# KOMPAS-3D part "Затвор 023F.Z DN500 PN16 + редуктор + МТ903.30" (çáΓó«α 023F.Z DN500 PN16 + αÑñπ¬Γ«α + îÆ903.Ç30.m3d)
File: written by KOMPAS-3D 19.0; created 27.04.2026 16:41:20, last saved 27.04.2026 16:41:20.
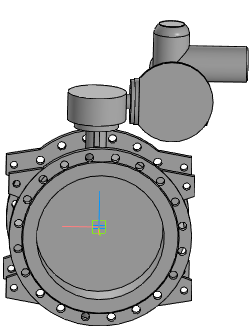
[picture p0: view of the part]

Document properties: Полное имя файла: ..\..\Затвор 023F.Z DN400-DN1600 + редуктор + МТ903\Затвор 023F.Z DN500 PN16 + редуктор + МТ903.А30.a3d

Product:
- Part/product: Затвор 023F.Z DN500 PN16 + редуктор + МТ903.30
    Масса: 478.605

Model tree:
1. Операция без истории:1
